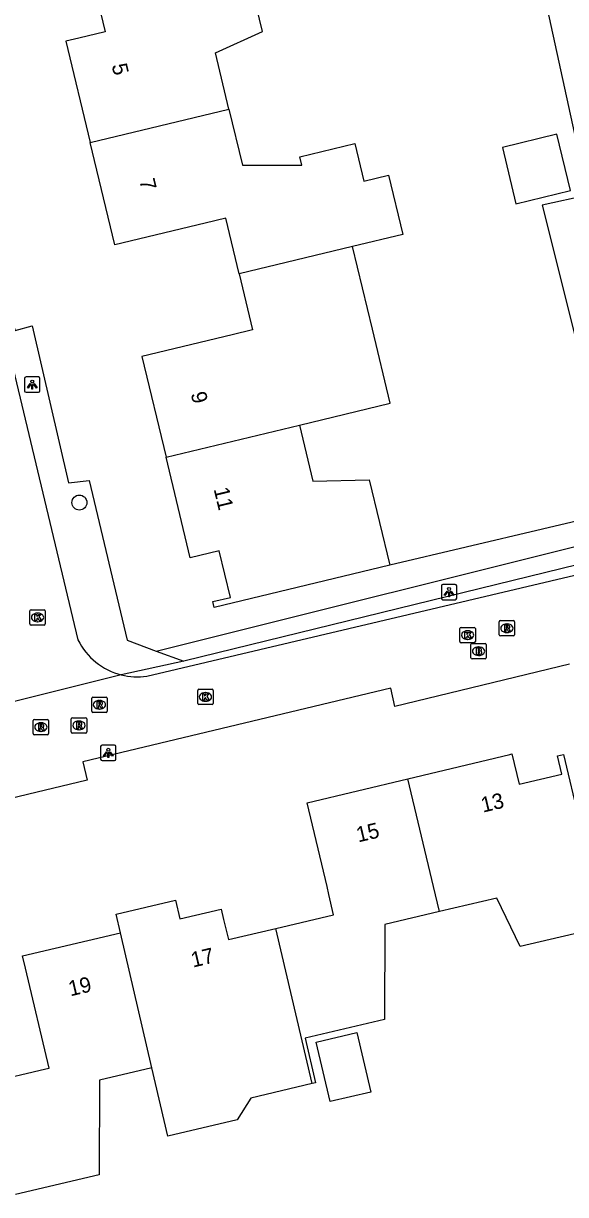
# Model space of a CAD drawing. Extents: x 157793 to 159380, y 380882 to 382313.
# Drawn here: x 158933.4 to 158968.6, y 381230 to 381306.1 of the extents above; entities that cross this region are included whole.
import ezdxf

# ---------------------------------------------------------------- set-up
doc = ezdxf.new("R2010")
doc.units = 0
for name, color, linetype in [('IMGEO_Boom', 7, 'Continuous'), ('IMGEO_Brandkraan', 7, 'Continuous'), ('IMGEO_Groenvoorziening', 7, 'Continuous'), ('IMGEO_Hek', 7, 'Continuous'), ('IMGEO_Kolk', 7, 'Continuous'), ('IMGEO_Lichtpunt', 7, 'Continuous'), ('IMGEO_Pand', 7, 'Continuous'), ('IMGEO_Pand_nummerreeks', 7, 'Continuous'), ('IMGEO_Rijbaan_lokaal_open', 7, 'Continuous'), ('IMGEO_Rioolput', 7, 'Continuous'), ('IMGEO_Voetpad_open', 7, 'Continuous')]:
    doc.layers.add(name, color=color, linetype=linetype)

msp = doc.modelspace()

# ---------------------------------------------------------------- linework, layer by layer
at = {"layer": 'IMGEO_Boom'}
msp.add_circle((158937.014, 381274.972), 0.489, dxfattribs=at)
at = {"layer": 'IMGEO_Brandkraan'}
for p, q in [((158962.479, 381264.883), (158962.479, 381265.735)), ((158962.554, 381265.809), (158963.406, 381265.809)), ((158963.48, 381265.735), (158963.48, 381264.883)), ((158962.99, 381265.029), (158962.965, 381265.029)), ((158962.967, 381265.589), (158962.992, 381265.589)), ((158963.406, 381264.809), (158962.554, 381264.809))]:
    msp.add_line(p, q, dxfattribs=at)
for points in [[(158962.479, 381264.883), (158962.479, 381265.735)], [(158962.554, 381265.809), (158963.406, 381265.809)], [(158963.48, 381265.735), (158963.48, 381264.883)], [(158962.827, 381265.509), (158962.827, 381265.109), (158963.04, 381265.109)], [(158963.058, 381265.509), (158962.827, 381265.509)], [(158963.006, 381265.428), (158962.952, 381265.428), (158962.952, 381265.352)], [(158962.952, 381265.352), (158963.005, 381265.352)], [(158963.014, 381265.276), (158962.952, 381265.276), (158962.952, 381265.195)], [(158962.952, 381265.195), (158963.014, 381265.195)], [(158963.406, 381264.809), (158962.554, 381264.809)]]:
    msp.add_lwpolyline(points, dxfattribs=at)
for centre, radius, start, end in [((158962.556, 381265.733), 0.0765, 91.55205, 178.44795), ((158962.556, 381265.733), 0.0765, 91.55205, 178.44795), ((158963.404, 381265.733), 0.0765, 1.55205, 88.44795), ((158963.404, 381265.733), 0.0765, 1.55205, 88.44795), ((158963.007, 381265.39), 0.0379, 267.82845, 90.93552), ((158963.015, 381265.235), 0.0404, 269.87594, 90.50774), ((158963.046, 381265.36), 0.251, 268.66757, 293.53466), ((158963.062, 381265.364), 0.145, 59.4692, 91.53667), ((158963.087, 381265.411), 0.0922, 285.51372, 58.15012), ((158963.092, 381265.219), 0.105, 301.31148, 78.98903), ((158962.556, 381264.885), 0.0765, 181.55205, 268.44795), ((158962.556, 381264.885), 0.0765, 181.55205, 268.44795), ((158963.404, 381264.885), 0.0765, 271.55205, 358.44795), ((158963.404, 381264.885), 0.0765, 271.55205, 358.44795)]:
    msp.add_arc(centre, radius, start, end, dxfattribs=at)
for centre, major_axis, ratio, start_param, end_param in [((158962.966, 381265.309), (-0.387, 0.002), 0.722429, 4.712389, 7.853982), ((158962.991, 381265.309), (-0.39, 0.002), 0.717154, 1.570796, 4.712389)]:
    msp.add_ellipse(centre, major_axis=major_axis, ratio=ratio, start_param=start_param, end_param=end_param, dxfattribs=at)
at = {"layer": 'IMGEO_Groenvoorziening'}
for points in [[(158962.67, 381326.045), (158967.31, 381307.715), (158970.089, 381294.961), (158967.118, 381294.307), (158972.103, 381274.414), (158972.479, 381272.913)], [(158942.018, 381265.319), (158972.479, 381272.913)]]:
    msp.add_lwpolyline(points, dxfattribs=at)
at = {"layer": 'IMGEO_Hek'}
msp.add_lwpolyline([(158972.103, 381274.414), (158957.198, 381270.897)], dxfattribs=at)
at = {"layer": 'IMGEO_Kolk'}
for p, q in [((158933.871, 381268.005), (158934.723, 381268.005)), ((158933.796, 381267.079), (158933.796, 381267.931)), ((158934.307, 381267.225), (158934.282, 381267.225)), ((158934.284, 381267.785), (158934.309, 381267.785)), ((158934.797, 381267.931), (158934.797, 381267.079)), ((158934.723, 381267.005), (158933.871, 381267.005)), ((158961.769, 381265.929), (158961.769, 381266.781)), ((158961.844, 381266.855), (158962.696, 381266.855)), ((158962.257, 381266.635), (158962.282, 381266.635)), ((158962.77, 381266.781), (158962.77, 381265.929)), ((158962.696, 381265.855), (158961.844, 381265.855)), ((158962.28, 381266.075), (158962.255, 381266.075)), ((158944.717, 381261.906), (158944.717, 381262.758)), ((158944.792, 381262.832), (158945.644, 381262.832)), ((158945.718, 381262.758), (158945.718, 381261.906)), ((158945.228, 381262.052), (158945.203, 381262.052)), ((158945.205, 381262.612), (158945.23, 381262.612)), ((158945.644, 381261.832), (158944.792, 381261.832))]:
    msp.add_line(p, q, dxfattribs=at)
for points in [[(158933.871, 381268.005), (158934.723, 381268.005)], [(158933.796, 381267.079), (158933.796, 381267.931)], [(158934.117, 381267.705), (158934.24, 381267.705), (158934.24, 381267.554), (158934.37, 381267.705), (158934.534, 381267.705), (158934.388, 381267.554), (158934.541, 381267.305), (158934.389, 381267.305), (158934.304, 381267.469), (158934.24, 381267.402), (158934.24, 381267.305), (158934.117, 381267.305), (158934.117, 381267.705)], [(158934.797, 381267.931), (158934.797, 381267.079)], [(158934.723, 381267.005), (158933.871, 381267.005)], [(158961.769, 381265.929), (158961.769, 381266.781)], [(158961.844, 381266.855), (158962.696, 381266.855)], [(158962.09, 381266.555), (158962.213, 381266.555), (158962.213, 381266.404), (158962.343, 381266.555), (158962.507, 381266.555), (158962.361, 381266.404), (158962.514, 381266.155), (158962.362, 381266.155), (158962.277, 381266.319), (158962.213, 381266.252), (158962.213, 381266.155), (158962.09, 381266.155), (158962.09, 381266.555)], [(158962.77, 381266.781), (158962.77, 381265.929)], [(158962.696, 381265.855), (158961.844, 381265.855)], [(158944.717, 381261.906), (158944.717, 381262.758)], [(158944.792, 381262.832), (158945.644, 381262.832)], [(158945.718, 381262.758), (158945.718, 381261.906)], [(158945.038, 381262.532), (158945.161, 381262.532), (158945.161, 381262.381), (158945.291, 381262.532), (158945.455, 381262.532), (158945.309, 381262.381), (158945.462, 381262.132), (158945.31, 381262.132), (158945.225, 381262.296), (158945.161, 381262.229), (158945.161, 381262.132), (158945.038, 381262.132), (158945.038, 381262.532)], [(158945.644, 381261.832), (158944.792, 381261.832)]]:
    msp.add_lwpolyline(points, dxfattribs=at)
for centre, start, end in [((158933.873, 381267.929), 91.55205, 178.44795), ((158933.873, 381267.929), 91.55205, 178.44795), ((158934.721, 381267.929), 1.55205, 88.44795), ((158934.721, 381267.929), 1.55205, 88.44795), ((158933.873, 381267.081), 181.55205, 268.44795), ((158933.873, 381267.081), 181.55205, 268.44795), ((158934.721, 381267.081), 271.55205, 358.44795), ((158934.721, 381267.081), 271.55205, 358.44795), ((158961.846, 381266.779), 91.55205, 178.44795), ((158961.846, 381266.779), 91.55205, 178.44795), ((158962.694, 381266.779), 1.55205, 88.44795), ((158962.694, 381266.779), 1.55205, 88.44795), ((158961.846, 381265.931), 181.55205, 268.44795), ((158961.846, 381265.931), 181.55205, 268.44795), ((158962.694, 381265.931), 271.55205, 358.44795), ((158962.694, 381265.931), 271.55205, 358.44795), ((158944.794, 381262.756), 91.55205, 178.44795), ((158944.794, 381262.756), 91.55205, 178.44795), ((158945.642, 381262.756), 1.55205, 88.44795), ((158945.642, 381262.756), 1.55205, 88.44795), ((158944.794, 381261.908), 181.55205, 268.44795), ((158944.794, 381261.908), 181.55205, 268.44795), ((158945.642, 381261.908), 271.55205, 358.44795), ((158945.642, 381261.908), 271.55205, 358.44795)]:
    msp.add_arc(centre, 0.0765, start, end, dxfattribs=at)
for centre, major_axis, ratio, start_param, end_param in [((158934.283, 381267.505), (-0.387, 0.002), 0.722429, 4.712389, 7.853982), ((158934.308, 381267.505), (-0.39, 0.002), 0.717154, 1.570796, 4.712389), ((158962.256, 381266.355), (-0.387, 0.002), 0.722429, 4.712389, 7.853982), ((158962.281, 381266.355), (-0.39, 0.002), 0.717154, 1.570796, 4.712389), ((158945.204, 381262.332), (-0.387, 0.002), 0.722429, 4.712389, 7.853982), ((158945.229, 381262.332), (-0.39, 0.002), 0.717154, 1.570796, 4.712389)]:
    msp.add_ellipse(centre, major_axis=major_axis, ratio=ratio, start_param=start_param, end_param=end_param, dxfattribs=at)
at = {"layer": 'IMGEO_Lichtpunt'}
for p, q in [((158933.45, 381283.044), (158933.45, 381282.237)), ((158933.45, 381283.044), (158933.45, 381282.237)), ((158934.352, 381283.139), (158933.544, 381283.139)), ((158934.352, 381283.139), (158933.544, 381283.139)), ((158934.446, 381282.237), (158934.446, 381283.044)), ((158934.446, 381282.237), (158934.446, 381283.044)), ((158933.544, 381282.143), (158934.352, 381282.143)), ((158933.544, 381282.143), (158934.352, 381282.143)), ((158960.564, 381269.557), (158960.564, 381268.75)), ((158960.564, 381269.557), (158960.564, 381268.75)), ((158961.466, 381269.652), (158960.658, 381269.652)), ((158961.466, 381269.652), (158960.658, 381269.652)), ((158961.56, 381268.75), (158961.56, 381269.557)), ((158961.56, 381268.75), (158961.56, 381269.557)), ((158960.658, 381268.656), (158961.466, 381268.656)), ((158960.658, 381268.656), (158961.466, 381268.656)), ((158938.398, 381259.101), (158938.398, 381258.294)), ((158938.398, 381259.101), (158938.398, 381258.294)), ((158939.3, 381259.196), (158938.492, 381259.196)), ((158939.3, 381259.196), (158938.492, 381259.196)), ((158939.394, 381258.294), (158939.394, 381259.101)), ((158939.394, 381258.294), (158939.394, 381259.101)), ((158938.492, 381258.2), (158939.3, 381258.2)), ((158938.492, 381258.2), (158939.3, 381258.2))]:
    msp.add_line(p, q, dxfattribs=at)
for points in [[(158933.824, 381282.708), (158933.863, 381282.68), (158933.675, 381282.418), (158933.637, 381282.445), (158933.824, 381282.708)], [(158933.926, 381282.66), (158933.973, 381282.66), (158933.973, 381282.338), (158933.926, 381282.338), (158933.926, 381282.66)], [(158934.036, 381282.68), (158934.074, 381282.707), (158934.261, 381282.445), (158934.222, 381282.417), (158934.036, 381282.68)], [(158960.938, 381269.221), (158960.977, 381269.193), (158960.789, 381268.931), (158960.751, 381268.958), (158960.938, 381269.221)], [(158961.04, 381269.173), (158961.087, 381269.173), (158961.087, 381268.851), (158961.04, 381268.851), (158961.04, 381269.173)], [(158961.15, 381269.193), (158961.188, 381269.22), (158961.375, 381268.958), (158961.336, 381268.93), (158961.15, 381269.193)], [(158938.772, 381258.765), (158938.811, 381258.737), (158938.623, 381258.475), (158938.585, 381258.502), (158938.772, 381258.765)], [(158938.874, 381258.717), (158938.921, 381258.717), (158938.921, 381258.395), (158938.874, 381258.395), (158938.874, 381258.717)], [(158938.984, 381258.737), (158939.022, 381258.764), (158939.209, 381258.502), (158939.17, 381258.474), (158938.984, 381258.737)]]:
    msp.add_lwpolyline(points, dxfattribs=at)
for centre in [(158933.949, 381282.842), (158961.063, 381269.355), (158938.897, 381258.899)]:
    msp.add_circle(centre, 0.0994, dxfattribs=at)
for centre, start, end in [((158933.544, 381283.044), 90, 180), ((158933.544, 381283.044), 90, 180), ((158934.352, 381283.044), 0, 90), ((158934.352, 381283.044), 0, 90), ((158933.544, 381282.237), 180, 270), ((158933.544, 381282.237), 180, 270), ((158934.352, 381282.237), 270, 0), ((158934.352, 381282.237), 270, 360), ((158960.658, 381269.557), 90, 180), ((158960.658, 381269.557), 90, 180), ((158961.466, 381269.557), 0, 90), ((158961.466, 381269.557), 0, 90), ((158960.658, 381268.75), 180, 270), ((158960.658, 381268.75), 180, 270), ((158961.466, 381268.75), 270, 0), ((158961.466, 381268.75), 270, 360), ((158938.492, 381259.101), 90, 180), ((158938.492, 381259.101), 90, 180), ((158939.3, 381259.101), 0, 90), ((158939.3, 381259.101), 0, 90), ((158938.492, 381258.294), 180, 270), ((158938.492, 381258.294), 180, 270), ((158939.3, 381258.294), 270, 0), ((158939.3, 381258.294), 270, 360)]:
    msp.add_arc(centre, 0.0946, start, end, dxfattribs=at)
at = {"layer": 'IMGEO_Pand'}
for points in [[(158946.742, 381300.56), (158945.863, 381304.211), (158948.917, 381305.611), (158947.581, 381311.16), (158937.916, 381308.832), (158938.697, 381305.589), (158936.985, 381305.177), (158936.138, 381304.973), (158937.723, 381298.391)], [(158937.723, 381298.391), (158946.742, 381300.56)], [(158946.742, 381300.56), (158947.622, 381296.906), (158951.493, 381296.918), (158951.361, 381297.463), (158954.923, 381298.321), (158955.511, 381295.879), (158957.127, 381296.268), (158958.057, 381292.404), (158954.779, 381291.614)], [(158964.528, 381298.067), (158965.41, 381294.403), (158968.957, 381295.256), (158968.075, 381298.921), (158964.528, 381298.067)], [(158947.409, 381289.84), (158946.534, 381293.473), (158945.2, 381293.152), (158939.325, 381291.738), (158937.723, 381298.391)], [(158954.779, 381291.614), (158947.409, 381289.84)], [(158951.327, 381280.016), (158957.23, 381281.438), (158956.072, 381286.246), (158954.779, 381291.614)], [(158947.409, 381289.84), (158948.284, 381286.207), (158946.95, 381285.886), (158941.076, 381284.471), (158942.652, 381277.928)], [(158942.652, 381277.928), (158951.327, 381280.016)], [(158951.327, 381280.016), (158952.206, 381276.367), (158955.86, 381276.452), (158957.198, 381270.897), (158945.787, 381268.149), (158945.695, 381268.533), (158946.843, 381268.809), (158946.113, 381271.84), (158944.227, 381271.386), (158942.652, 381277.928)], [(158958.387, 381257.014), (158965.004, 381258.596), (158965.146, 381258.63), (158965.618, 381256.655), (158968.404, 381257.321), (158968.12, 381258.507), (158968.5, 381258.597), (158970.55, 381250), (158971.172, 381247.394), (158965.691, 381246.107), (158964.174, 381249.253), (158960.432, 381248.374)], [(158949.8, 381247.278), (158953.544, 381248.157), (158953.249, 381249.478), (158953.125, 381250), (158951.83, 381255.447), (158958.387, 381257.014)], [(158960.432, 381248.374), (158960.047, 381250), (158958.387, 381257.014)], [(158939.683, 381246.994), (158939.397, 381248.211), (158943.272, 381249.12), (158943.558, 381247.903), (158946.24, 381248.533), (158946.396, 381247.869), (158946.706, 381246.551), (158949.8, 381247.278)], [(158960.432, 381248.374), (158956.884, 381247.541), (158956.872, 381241.365), (158951.701, 381240.151), (158952.384, 381237.241), (158952.166, 381237.19)], [(158931.141, 381237.283), (158934.822, 381238.147), (158935.039, 381238.198), (158933.515, 381244.695), (158933.325, 381245.501), (158939.683, 381246.994)], [(158941.737, 381238.216), (158939.683, 381246.994)], [(158952.166, 381237.19), (158949.8, 381247.278)], [(158952.424, 381239.886), (158955.056, 381240.504), (158955.964, 381236.634), (158953.331, 381236.016), (158952.424, 381239.886)], [(158941.737, 381238.216), (158938.32, 381237.413), (158938.309, 381231.254), (158932.856, 381229.974)], [(158952.166, 381237.19), (158948.163, 381236.25), (158947.288, 381234.838), (158942.775, 381233.782), (158941.737, 381238.216)]]:
    msp.add_lwpolyline(points, dxfattribs=at)
at = {"layer": 'IMGEO_Rijbaan_lokaal_open'}
for points in [[(158936.925, 381266.042), (158931.1, 381290.379), (158927.478, 381293.119), (158911.935, 381304.441), (158906.943, 381324.962), (158906.622, 381326.256)], [(158941.405, 381263.678), (158969.621, 381270.34)], [(158968.906, 381264.456), (158957.537, 381261.722), (158957.278, 381262.898), (158937.248, 381258.103), (158937.52, 381256.931), (158917.019, 381252), (158917.231, 381250.819), (158885.275, 381243.32)], [(158939.738, 381263.77), (158932.526, 381261.978)]]:
    msp.add_lwpolyline(points, dxfattribs=at)
for centre, radius, start, end in [((158940.802, 381267.965), 4.328, 206.37877, 255.76709), ((158940.806, 381267.972), 4.335, 255.73967, 277.94255)]:
    msp.add_arc(centre, radius, start, end, dxfattribs=at)
at = {"layer": 'IMGEO_Rioolput'}
for p, q in [((158964.325, 381266.374), (158964.325, 381267.226)), ((158964.4, 381267.3), (158965.252, 381267.3)), ((158965.326, 381267.226), (158965.326, 381266.374)), ((158964.836, 381266.52), (158964.811, 381266.52)), ((158964.813, 381267.08), (158964.838, 381267.08)), ((158965.252, 381266.3), (158964.4, 381266.3)), ((158937.821, 381261.399), (158937.821, 381262.251)), ((158937.896, 381262.325), (158938.748, 381262.325)), ((158938.309, 381262.105), (158938.334, 381262.105)), ((158938.822, 381262.251), (158938.822, 381261.399)), ((158938.748, 381261.325), (158937.896, 381261.325)), ((158938.332, 381261.545), (158938.307, 381261.545)), ((158934.013, 381259.946), (158934.013, 381260.798)), ((158934.088, 381260.872), (158934.94, 381260.872)), ((158934.501, 381260.652), (158934.526, 381260.652)), ((158935.014, 381260.798), (158935.014, 381259.946)), ((158936.488, 381260.058), (158936.488, 381260.91)), ((158936.563, 381260.984), (158937.415, 381260.984)), ((158936.976, 381260.764), (158937.001, 381260.764)), ((158937.489, 381260.91), (158937.489, 381260.058)), ((158934.94, 381259.872), (158934.088, 381259.872)), ((158934.524, 381260.092), (158934.499, 381260.092)), ((158937.415, 381259.984), (158936.563, 381259.984)), ((158936.999, 381260.204), (158936.974, 381260.204))]:
    msp.add_line(p, q, dxfattribs=at)
for points in [[(158964.325, 381266.374), (158964.325, 381267.226)], [(158964.4, 381267.3), (158965.252, 381267.3)], [(158965.326, 381267.226), (158965.326, 381266.374)], [(158964.914, 381266.998), (158964.662, 381267), (158964.662, 381266.6)], [(158964.662, 381266.6), (158964.786, 381266.6), (158964.786, 381266.762), (158964.797, 381266.762)], [(158964.84, 381266.919), (158964.786, 381266.919), (158964.786, 381266.838)], [(158964.786, 381266.838), (158964.838, 381266.838)], [(158964.844, 381266.733), (158964.915, 381266.6), (158965.055, 381266.6), (158964.99, 381266.726)], [(158965.252, 381266.3), (158964.4, 381266.3)], [(158937.821, 381261.399), (158937.821, 381262.251)], [(158937.896, 381262.325), (158938.748, 381262.325)], [(158938.41, 381262.023), (158938.158, 381262.025), (158938.158, 381261.625)], [(158938.336, 381261.944), (158938.282, 381261.944), (158938.282, 381261.863)], [(158938.822, 381262.251), (158938.822, 381261.399)], [(158938.748, 381261.325), (158937.896, 381261.325)], [(158938.158, 381261.625), (158938.282, 381261.625), (158938.282, 381261.787), (158938.293, 381261.787)], [(158938.282, 381261.863), (158938.334, 381261.863)], [(158938.34, 381261.758), (158938.411, 381261.625), (158938.551, 381261.625), (158938.486, 381261.751)], [(158934.013, 381259.946), (158934.013, 381260.798)], [(158934.088, 381260.872), (158934.94, 381260.872)], [(158934.602, 381260.57), (158934.35, 381260.572), (158934.35, 381260.172)], [(158934.528, 381260.491), (158934.474, 381260.491), (158934.474, 381260.41)], [(158934.474, 381260.41), (158934.526, 381260.41)], [(158935.014, 381260.798), (158935.014, 381259.946)], [(158936.488, 381260.058), (158936.488, 381260.91)], [(158936.563, 381260.984), (158937.415, 381260.984)], [(158937.077, 381260.682), (158936.825, 381260.684), (158936.825, 381260.284)], [(158936.825, 381260.284), (158936.949, 381260.284), (158936.949, 381260.446), (158936.96, 381260.446)], [(158937.003, 381260.603), (158936.949, 381260.603), (158936.949, 381260.522)], [(158936.949, 381260.522), (158937.001, 381260.522)], [(158937.007, 381260.417), (158937.078, 381260.284), (158937.218, 381260.284), (158937.153, 381260.41)], [(158937.489, 381260.91), (158937.489, 381260.058)], [(158934.94, 381259.872), (158934.088, 381259.872)], [(158934.35, 381260.172), (158934.474, 381260.172), (158934.474, 381260.334), (158934.485, 381260.334)], [(158934.532, 381260.305), (158934.603, 381260.172), (158934.743, 381260.172), (158934.678, 381260.298)], [(158937.415, 381259.984), (158936.563, 381259.984)]]:
    msp.add_lwpolyline(points, dxfattribs=at)
for centre, radius, start, end in [((158964.402, 381267.224), 0.0765, 91.55205, 178.44795), ((158964.402, 381267.224), 0.0765, 91.55205, 178.44795), ((158965.25, 381267.224), 0.0765, 1.55205, 88.44795), ((158965.25, 381267.224), 0.0765, 1.55205, 88.44795), ((158964.796, 381266.709), 0.0533, 26.02933, 88.69889), ((158964.822, 381267.027), 0.19, 274.7715, 282.96867), ((158964.846, 381266.823), 0.0964, 77.00612, 93.18647), ((158964.86, 381266.88), 0.0378, 276.66336, 79.67722), ((158964.913, 381266.888), 0.109, 350.36119, 89.41601), ((158964.911, 381266.888), 0.112, 277.58423, 350.98172), ((158964.895, 381266.673), 0.108, 29.51342, 73.79051), ((158964.402, 381266.376), 0.0765, 181.55205, 268.44795), ((158964.402, 381266.376), 0.0765, 181.55205, 268.44795), ((158965.25, 381266.376), 0.0765, 271.55205, 358.44795), ((158965.25, 381266.376), 0.0765, 271.55205, 358.44795), ((158937.898, 381262.249), 0.0765, 91.55205, 178.44795), ((158937.898, 381262.249), 0.0765, 91.55205, 178.44795), ((158938.342, 381261.848), 0.0964, 77.00612, 93.18647), ((158938.356, 381261.905), 0.0378, 276.66336, 79.67722), ((158938.409, 381261.913), 0.109, 350.36119, 89.41601), ((158938.407, 381261.913), 0.112, 277.58423, 350.98172), ((158938.746, 381262.249), 0.0765, 1.55205, 88.44795), ((158938.746, 381262.249), 0.0765, 1.55205, 88.44795), ((158937.898, 381261.401), 0.0765, 181.55205, 268.44795), ((158937.898, 381261.401), 0.0765, 181.55205, 268.44795), ((158938.292, 381261.734), 0.0533, 26.02933, 88.69889), ((158938.318, 381262.052), 0.19, 274.7715, 282.96867), ((158938.391, 381261.698), 0.108, 29.51342, 73.79051), ((158938.746, 381261.401), 0.0765, 271.55205, 358.44795), ((158938.746, 381261.401), 0.0765, 271.55205, 358.44795), ((158934.09, 381260.796), 0.0765, 91.55205, 178.44795), ((158934.09, 381260.796), 0.0765, 91.55205, 178.44795), ((158934.51, 381260.599), 0.19, 274.7715, 282.96867), ((158934.534, 381260.395), 0.0964, 77.00612, 93.18647), ((158934.548, 381260.452), 0.0378, 276.66336, 79.67722), ((158934.601, 381260.46), 0.109, 350.36119, 89.41601), ((158934.599, 381260.46), 0.112, 277.58423, 350.98172), ((158934.938, 381260.796), 0.0765, 1.55205, 88.44795), ((158934.938, 381260.796), 0.0765, 1.55205, 88.44795), ((158936.565, 381260.908), 0.0765, 91.55205, 178.44795), ((158936.565, 381260.908), 0.0765, 91.55205, 178.44795), ((158936.959, 381260.393), 0.0533, 26.02933, 88.69889), ((158936.985, 381260.711), 0.19, 274.7715, 282.96867), ((158937.009, 381260.507), 0.0964, 77.00612, 93.18647), ((158937.023, 381260.564), 0.0378, 276.66336, 79.67722), ((158937.076, 381260.572), 0.109, 350.36119, 89.41601), ((158937.074, 381260.572), 0.112, 277.58423, 350.98172), ((158937.058, 381260.357), 0.108, 29.51342, 73.79051), ((158937.413, 381260.908), 0.0765, 1.55205, 88.44795), ((158937.413, 381260.908), 0.0765, 1.55205, 88.44795), ((158934.09, 381259.948), 0.0765, 181.55205, 268.44795), ((158934.09, 381259.948), 0.0765, 181.55205, 268.44795), ((158934.484, 381260.281), 0.0533, 26.02933, 88.69889), ((158934.583, 381260.245), 0.108, 29.51342, 73.79051), ((158934.938, 381259.948), 0.0765, 271.55205, 358.44795), ((158934.938, 381259.948), 0.0765, 271.55205, 358.44795), ((158936.565, 381260.06), 0.0765, 181.55205, 268.44795), ((158936.565, 381260.06), 0.0765, 181.55205, 268.44795), ((158937.413, 381260.06), 0.0765, 271.55205, 358.44795), ((158937.413, 381260.06), 0.0765, 271.55205, 358.44795)]:
    msp.add_arc(centre, radius, start, end, dxfattribs=at)
for centre, major_axis, ratio, start_param, end_param in [((158964.812, 381266.8), (-0.387, 0.002), 0.722429, 4.712389, 7.853982), ((158964.837, 381266.8), (-0.39, 0.002), 0.717154, 1.570796, 4.712389), ((158938.308, 381261.825), (-0.387, 0.002), 0.722429, 4.712389, 7.853982), ((158938.333, 381261.825), (-0.39, 0.002), 0.717154, 1.570796, 4.712389), ((158934.5, 381260.372), (-0.387, 0.002), 0.722429, 4.712389, 7.853982), ((158934.525, 381260.372), (-0.39, 0.002), 0.717154, 1.570796, 4.712389), ((158936.975, 381260.484), (-0.387, 0.002), 0.722429, 4.712389, 7.853982), ((158937, 381260.484), (-0.39, 0.002), 0.717154, 1.570796, 4.712389)]:
    msp.add_ellipse(centre, major_axis=major_axis, ratio=ratio, start_param=start_param, end_param=end_param, dxfattribs=at)
at = {"layer": 'IMGEO_Voetpad_open'}
for points in [[(158907.649, 381326.527), (158910.886, 381313.326), (158912.546, 381313.735), (158917.189, 381303.806), (158919.179, 381304.287), (158919.257, 381304.369), (158920.148, 381301.124), (158927.673, 381295.778), (158929.242, 381296.29), (158932.843, 381286.154), (158933.942, 381286.459), (158936.317, 381276.259), (158937.652, 381276.407), (158940.117, 381266.025), (158942.018, 381265.319)], [(158969.621, 381270.34), (158969.472, 381270.936), (158943.817, 381264.651)], [(158942.018, 381265.319), (158943.817, 381264.651)], [(158943.817, 381264.651), (158939.738, 381263.77)]]:
    msp.add_lwpolyline(points, dxfattribs=at)

# ---------------------------------------------------------------- texts
at = {"layer": 'IMGEO_Pand_nummerreeks'}
for s, rotation, p in [('5', 283.53878, (158939.108, 381303.406)), ('7', 283.53872, (158940.909, 381295.922)), ('9', 283.54451, (158944.249, 381282.058)), ('11', 283.53647, (158945.744, 381275.851)), ('13', 13.44594, (158963.263, 381254.807)), ('15', 13.44053, (158955.157, 381252.87)), ('17', 13.20668, (158944.403, 381244.733)), ('19', 13.21241, (158936.429, 381242.861))]:
    msp.add_text(s, height=1, rotation=rotation, dxfattribs=at).set_placement(p)

doc.saveas('drawing.dxf')
